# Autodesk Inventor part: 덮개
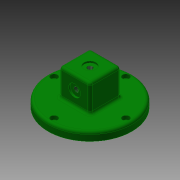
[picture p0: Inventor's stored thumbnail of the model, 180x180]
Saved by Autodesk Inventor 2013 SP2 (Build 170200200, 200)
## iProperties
Created: 2017-08
Part Number: 덮개
Material: 알루미늄 6061
Document SubType Name: Modeling
Designer: mduedu
Density: 1 g/cm^3
Author: mduedu
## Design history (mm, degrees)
sketch "스케치1"
  geometry: C1 r 49 at (0, 0); 1 further point
  constraints: 1 centre point, 1 coincident
  dimensions: "d55" = 98 diameter of C1
extrude "돌출1" new body sketch "스케치1" distance "d5" = 10; taper "d6" = 0 deg
sketch "스케치2"
  geometry: L1 (-18, -18)-(18, -18); L2 (18, -18)-(18, 18); L3 (18, 18)-(-18, 18); L4 (-18, 18)-(-18, -18); L5 (-18, -18)-(18, 18); L6 (18, -18)-(-18, 18); 1 further point
  constraints: 12 end point, 2 midpoint, 2 parallel, 2 perpendicular, 1 horizontal
  dimensions: "d7" = 36 distance of L2.end L3.end
extrude "돌출2" join sketch "스케치2" distance "d9" = 32; taper "d10" = 0 deg
sketch "스케치3"
  geometry: C1 r 37 at (0, 0); 1 further point
  constraints: 1 centre point, 1 coincident
  dimensions: "d56" = 74 diameter of C1
extrude "돌출3" join sketch "스케치3" distance "d12" = 7; taper "d13" = 0 deg
sketch "스케치4"
  geometry: C1 r 33 at (0, 0); 1 further point
  constraints: 1 centre point, 1 coincident
  dimensions: "d57" = 66 diameter of C1
extrude "돌출4" cut sketch "스케치4" distance "d16" = 6; taper "d17" = 0 deg
sketch "스케치5"
  geometry: C1 r 9 at (0, 0); 1 further point
  constraints: 1 centre point, 1 coincident
  dimensions: "d18" = 18 diameter of C1
extrude "돌출5" cut sketch "스케치5" distance "d19" = 34; taper "d20" = 0 deg
sketch "스케치6"
  geometry: 2 further points
  constraints: 1 coincident
hole "구멍1" sketch "스케치6" at (0, 0) diameter "d21" = 5.917; stored, may be unused: countersink angle "d25" = 90 deg, drill point angle "d27" = 118 deg; dims "d22" = 6, "d23" = 14, "d24" = 2, "d26" = 8
sketch "스케치7"
  geometry: L1 (-31, -10)-(67, -10) reference; 3 further points
  constraints: 1 midpoint, 1 vertical alignment
  dimensions: "d58" = 26 distance from line of point (18, 16) L1
hole "구멍2" sketch "스케치7" at (18, 16) diameter "d29" = 5.917; stored, may be unused: countersink angle "d33" = 90 deg, drill point angle "d35" = 118 deg; dims "d30" = 6, "d31" = 14, "d32" = 2, "d34" = 8
fillet "모깎기2" dims "d37" = 3
fillet "모깎기3" dims "d38" = 3
fillet "모깎기4" dims "d39" = 3
fillet "모깎기5" dims "d40" = 3
chamfer "모따기1" distance "d41" = 1; stored, may be unused: second distance "d42" = 2, angle "d43" = 45 deg
fillet "모깎기7" dims "d45" = 3
fillet "모깎기8" dims "d46" = 3
sketch "스케치10" dims "d59" = 84
  geometry: 3 further points
  constraints: 2 vertical alignment, 1 coincident, 2 other
hole "구멍4" sketch "스케치10" at (0, 42) diameter "d60" = 4.5; stored, may be unused: countersink angle "d64" = 90 deg, drill point angle "d66" = 118 deg; dims "d61" = 6, "d62" = 8, "d63" = 4.6, "d65" = 8
node "솔리드1"
pattern_circular "원형 패턴1" dims angle "d68" = 360 deg
